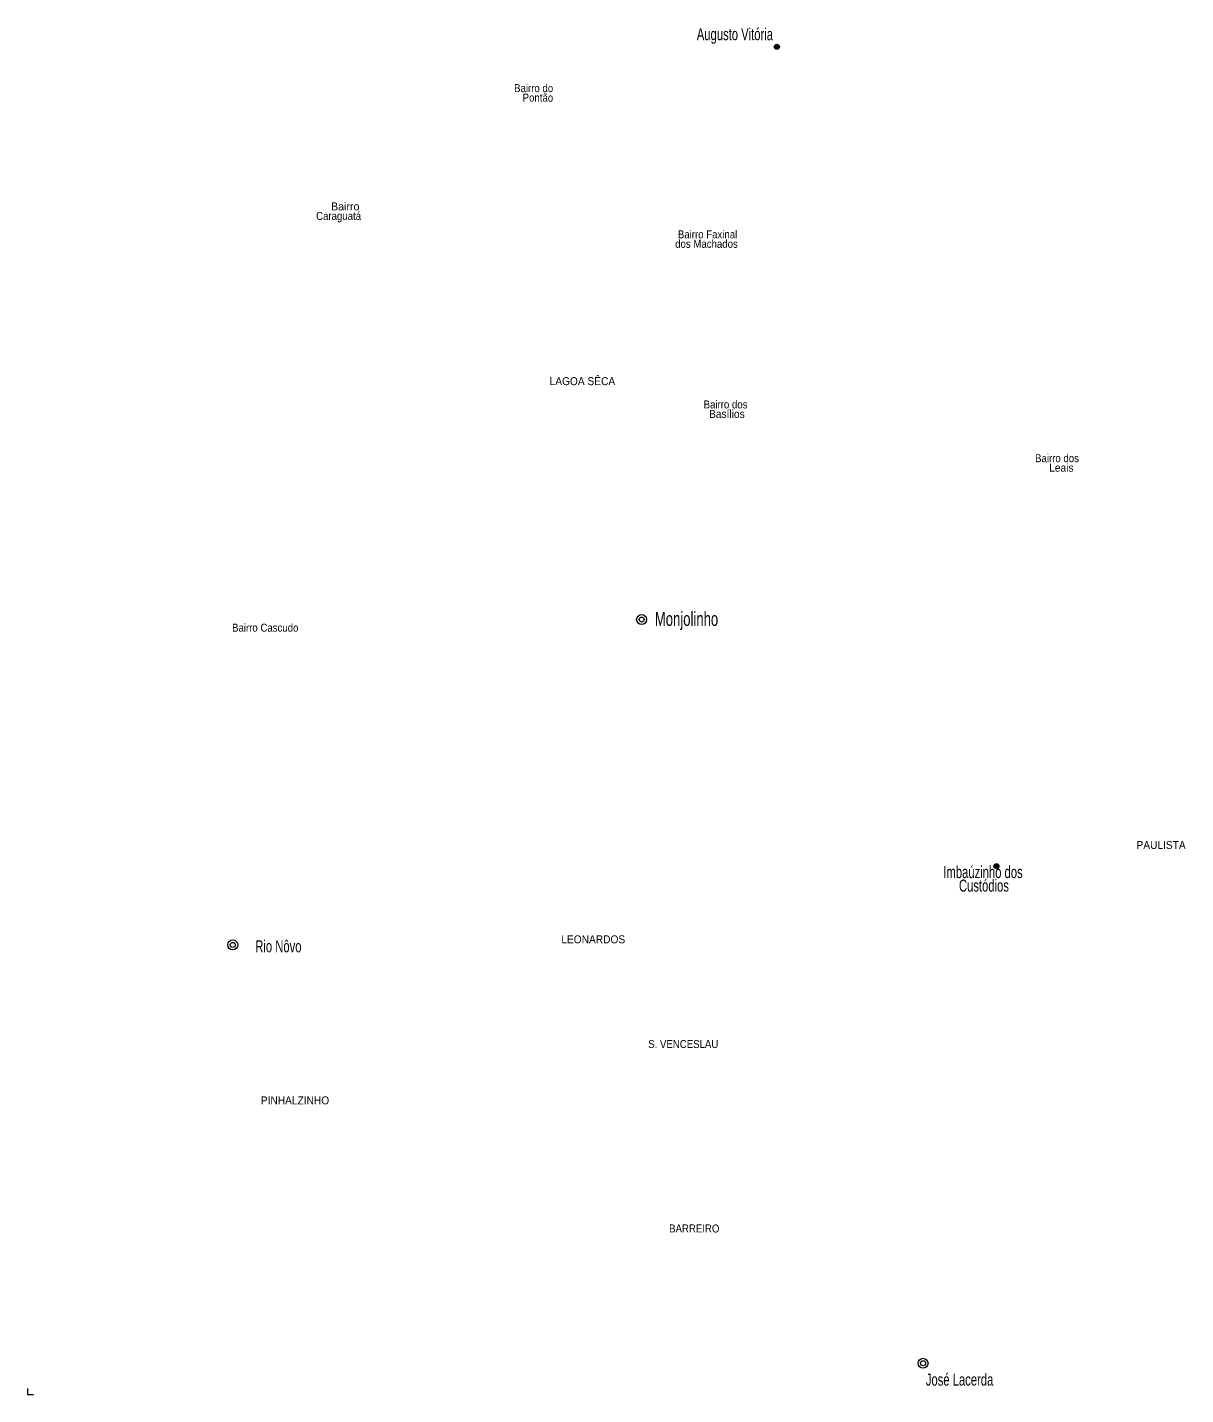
# Model space of a CAD drawing. Extents: x 500 to 550.9, y 7290.3 to 7345.7.
# Drawn here: x 500.01 to 523.17, y 7290.4 to 7317.74 of the extents above; entities that cross this region are included whole.
import ezdxf
from ezdxf.enums import TextEntityAlignment as Align

# ---------------------------------------------------------------- set-up
doc = ezdxf.new("R2010")
doc.units = 0
doc.header["$LTSCALE"] = 0.064
for name, color, linetype, lineweight in [('51', 7, 'Continuous', 13), ('52', 7, 'Continuous', 13), ('63', 7, 'Continuous', 13)]:
    doc.layers.add(name, color=color, linetype=linetype, lineweight=lineweight)
doc.layers.add('56', color=7, linetype='Continuous')
doc.layers.add('61', color=7, linetype='Continuous')

msp = doc.modelspace()

# ---------------------------------------------------------------- hatches: boundary and pattern name
at = {"layer": '52'}
for points in [[(515.05149, 7317.35216, 1), (514.95149, 7317.35216, 1)], [(519.43989, 7300.96676, 1), (519.33989, 7300.96676, 1)]]:
    msp.add_hatch(color=256, dxfattribs=at).paths.add_polyline_path(points)

# ---------------------------------------------------------------- linework, layer by layer
at = {"layer": '51'}
for centre, radius in [((512.296, 7305.89904), 0.1), ((512.296, 7305.89904), 0.05), ((504.12, 7299.39234), 0.1), ((504.12, 7299.39234), 0.05), ((517.9231, 7291.02594), 0.1), ((517.9231, 7291.02594), 0.05)]:
    msp.add_circle(centre, radius, dxfattribs=at)
at = {"layer": '52'}
for centre in [(515.00149, 7317.35216), (519.38989, 7300.96676)]:
    msp.add_circle(centre, 0.05, dxfattribs=at)
at = {"layer": '63'}
msp.add_lwpolyline([(500.0116, 7290.5219), (500.0116, 7290.3987), (500.133, 7290.3987)], dxfattribs=at)

# ---------------------------------------------------------------- texts
at = {"layer": '56'}
for s, width, p in [('LAGOA SÊCA', 0.95, (511.11125, 7310.5867)), ('PAULISTA', 0.95, (522.6835, 7301.3104)), ('LEONARDOS', 0.95, (511.3282, 7299.424)), ('S. VENCESLAU', 0.9, (513.128, 7297.3305)), ('PINHALZINHO', 0.95, (505.3641, 7296.2034)), ('BARREIRO', 0.9, (513.34785, 7293.6422))]:
    msp.add_text(s, height=0.16, dxfattribs=dict(at, width=width)).set_placement(p, align=Align.CENTER)
at = {"layer": '61'}
for s, height, width, p in [('Augusto Vitória', 0.24, 0.7, (514.9227, 7317.485)), ('Bairro do', 0.16, 0.9, (510.5266, 7316.4462)), ('  Pontão', 0.16, 0.9, (510.5266, 7316.2562)), ('Bairro dos', 0.16, 0.9, (514.4127, 7310.1212)), ('   Basílios ', 0.16, 0.95, (514.4127, 7309.9312))]:
    msp.add_text(s, height=height, dxfattribs=dict(at, width=width)).set_placement(p, align=Align.RIGHT)
for s, height, width, p in [('Caraguatá', 0.16, 0.9, (505.786, 7313.8909)), ('dos Machados', 0.16, 0.9, (512.9666, 7313.333)), (' Bairro Faxinal', 0.16, 0.9, (512.9666, 7313.523)), ('Bairro dos', 0.16, 0.9, (520.1634, 7309.0457)), ('     Leais', 0.16, 0.95, (520.1634, 7308.8557)), ('Bairro Cascudo', 0.16, 0.9, (504.105, 7305.6567)), ('Monjolinho', 0.28, 0.7, (512.5593, 7305.7719)), ('Imbaúzinho dos', 0.24, 0.7, (518.3292, 7300.7288)), ('     Custódios', 0.24, 0.7, (518.3292, 7300.4588)), ('Rio Nôvo', 0.24, 0.7, (504.5696, 7299.2445)), ('José Lacerda', 0.24, 0.7, (517.9791, 7290.5799))]:
    msp.add_text(s, height=height, dxfattribs=dict(at, width=width)).set_placement(p)
msp.add_text('     Bairro', height=0.16, dxfattribs=at).set_placement((505.786, 7314.0809))

doc.saveas('drawing.dxf')
